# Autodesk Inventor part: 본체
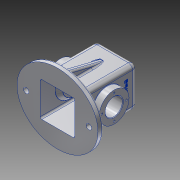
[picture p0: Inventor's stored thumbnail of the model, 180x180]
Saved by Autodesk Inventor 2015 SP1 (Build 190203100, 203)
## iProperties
Created: 2017-07
Part Number: 본체
Material: 알루미늄 6061
Document SubType Name: Modeling
Designer: C04
Density: 2.7 g/cm^3
Appearance: 알루미늄 - 평지
Mass: 889.343 g
Surface Area: 986.145 cm^2
Volume: 329.386 cm^3
Author: C04
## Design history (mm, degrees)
sketch "스케치1"
  geometry: L1 (0, 0)-(-75, 0); L2 (0, 0)-(0, 65); 1 further point; 1 other entity
  constraints: 4 end point, 1 coincident, 1 horizontal, 1 perpendicular, 4 other
  dimensions: "d32" = 75 distance of L1.start L1.end; "d33" = 65 distance of L1.start L2.end
extrude "돌출1" new body sketch "스케치1" distance "d1" = 10; taper "d2" = 0 deg
sketch "스케치7"
  geometry: L1 (-37, 37)-(37, 37); L2 (37, 37)-(37, -37); L3 (37, -37)-(-37, -37); L4 (-37, -37)-(-37, 37); L5 (-37, 37)-(37, -37); L6 (37, 37)-(-37, -37); 1 further point
  constraints: 12 end point, 2 midpoint, 2 parallel, 1 horizontal, 1 perpendicular
  dimensions: "d34" = 74 distance of L2.end L3.end; "d35" = 74 distance of L1.end L2.end
extrude "돌출6" join sketch "스케치7" distance "d36" = 100; taper "d37" = 0 deg
fillet "모깎기3" dims "d38" = 8
sketch "스케치8"
  geometry: L1 (-32, -32)-(32, -32); L2 (32, -32)-(32, 32); L3 (32, 32)-(-32, 32); L4 (-32, 32)-(-32, -32); L5 (-32, -32)-(32, 32); L6 (32, -32)-(-32, 32); 1 further point
  constraints: 12 end point, 2 midpoint, 2 parallel, 1 horizontal, 1 perpendicular
  dimensions: "d39" = 64 distance of L3.end L2.end; "d40" = 64 distance of L2.end L1.end
extrude "돌출7" cut sketch "스케치8" distance "d41" = 105; taper "d42" = 0 deg
sketch "스케치9"
  geometry: L1 (-3, -10)-(61, -10) reference; C1 r 27.5 at (29, 45); 4 further points
  constraints: 1 centre point, 1 midpoint, 1 vertical alignment
  dimensions: "d44" = 55 diameter of C1; "d45" = 55 distance from line of C1.centre L1
extrude "돌출8" join sketch "스케치9" distance "d46" = 13; taper "d47" = 0 deg
sketch "스케치10"
  geometry: L1 (-3, -10)-(61, -10) reference; C1 r 27.5 at (29, 45); 3 further points
  constraints: 1 centre point, 1 vertical alignment
  dimensions: "d48" = 55 diameter of C1; "d49" = 55 distance from line of C1.centre L1
extrude "돌출9" join sketch "스케치10" distance "d50" = 13; taper "d51" = 0 deg
fillet "모깎기5" dims "d52" = 3
sketch "스케치12"
  geometry: L1 (-32, 102)-(-32, 0) reference; L2 (32, 0)-(32, 102) reference; L3 (50, 27.5)-(50, 82.5) reference; L4 (-50, 82.5)-(-50, 27.5) reference; L5 (-32, 55)-(32, 55); L6 (25, 55)-(25, 75.5); L7 (-25, 75.5)-(-25, 55); L8 (-25, 75.5)-(-32, 82.5); L9 (25, 75.5)-(32, 82.5); L10 (29, 0)-(-29, 0) reference; 2 further points
  constraints: 10 end point, 6 point on line, 2 parallel, 1 horizontal alignment, 1 midpoint
  dimensions: "d53" = 7 distance between parallel lines of L2 L6; "d54" = 7 distance between parallel lines of L1 L7; "d55" = 55 diameter of L8.end L5; "d56" = 55 diameter of L9.end L5; "d57" = 135 deg angle of L1 L8; "d58" = 135 deg angle of L2 L9; "d59" = 55 distance between parallel lines of L5 L10 (derived)
revolve "회전2" sketch "스케치12" stored, may be unused: angle "d60" = 90 deg
fillet "모깎기6" dims "d61" = 0.5
sketch "스케치13"
  geometry: C1 r 27.5 at (0, 0) reference; 2 further points
  constraints: 1 vertical alignment
  dimensions: "d62" = 22.5 distance of point (0, 22.5) C1.centre
hole "구멍1" sketch "스케치13" at (0, 22.5) diameter "d63" = 3.242; stored, may be unused: countersink angle "d67" = 90 deg, drill point angle "d69" = 118 deg; dims "d64" = 8, "d65" = 4, "d66" = 2, "d68" = 10
sketch "스케치14"
  geometry: C1 r 20.293 at (0, 0) reference; 2 further points
  constraints: 1 vertical alignment
  dimensions: "d73" = 22.5 distance of C1.centre point (0, 22.5)
hole "구멍2" sketch "스케치14" at (0, 22.5) diameter "d74" = 3.242; stored, may be unused: countersink angle "d78" = 90 deg, drill point angle "d80" = 118 deg; dims "d75" = 8, "d76" = 4, "d77" = 2, "d79" = 10
hole "구멍3" diameter "d86" = 32; stored, may be unused: countersink angle "d90" = 90 deg, drill point angle "d92" = 0 deg; dims "d84" = 10, "d85" = 10, "d87" = 8, "d88" = 4, "d89" = 2, "d91" = 10
sketch "스케치15"
  geometry: L1 (-20, 20)-(20, 20); L2 (20, 20)-(20, -20); L3 (20, -20)-(-20, -20); L4 (-20, -20)-(-20, 20); L5 (-20, 20)-(20, -20); L6 (20, 20)-(-20, -20); 1 further point
  constraints: 12 end point, 2 midpoint, 2 parallel, 1 horizontal, 1 perpendicular
  dimensions: "d134" = 40 distance of L2.end L3.end; "d135" = 40 distance of L1.end L2.end
extrude "돌출10" join sketch "스케치15" distance "d94" = 10; taper "d95" = -5 deg
chamfer "모따기1" distance "d105" = 1; stored, may be unused: second distance "d106" = 2, angle "d107" = 45 deg
sketch "스케치17"
  geometry: 3 further points
  constraints: 2 horizontal alignment
  dimensions: "d108" = 116 distance of point (58, 0) point (-58, 0); "d109" = 58 distance of point (0, 0) point (-58, 0)
hole "구멍5" sketch "스케치17" at (-58, 0), (58, 0) diameter "d110" = 10; stored, may be unused: countersink angle "d114" = 90 deg, drill point angle "d116" = 0 deg; dims "d111" = 8, "d112" = 28, "d113" = 4, "d115" = 30
sketch "스케치18"
  geometry: L1 (10, 55)-(82.194, 37); 1 further point
  constraints: 2 end point
  dimensions: "d119" = 55.78548 distance from line of point (0, 0) L1; "d120" = 90.13802 distance of point (0, 0) L1.end; "d121" = 55.9017 distance of point (0, 0) L1.start; "d122" = 55 vertical distance of point (0, 0) L1.start
feature "리브1" sketch "스케치18" dims "d123" = 1, "d124" = 10, "d125" = 0, "d126" = 0, "d127" = 1, "d128" = 1
fillet "모깎기7" dims "d129" = 3
fillet "모깎기8" dims "d130" = 3
fillet "모깎기9" dims "d131" = 0.5
fillet "모깎기11" dims "d133" = 3
sketch "스케치19"
  geometry: 2 further points
  constraints: 1 coincident
hole "구멍6" sketch "스케치19" at (0, 0) diameter "d136" = 21; stored, may be unused: countersink angle "d140" = 90 deg, drill point angle "d142" = 0 deg; dims "d137" = 8, "d138" = 28, "d139" = 4, "d141" = 30
fillet "모깎기12" dims "d143" = 3
sketch "스케치20"
  geometry: L1 (45.137, 18)-(12.863, 18) reference; L2 (66, -89)-(66, 0) reference; 2 further points
  constraints: 1 other
  dimensions: "d144" = 30 distance from line of L1 point (29, -12); "d145" = 37 distance from line of L2 point (29, -12)
feature "엠보싱1" sketch "스케치20" dims "d146" = 0.5, "d147" = 0
node "솔리드1"
pattern_circular "원형 패턴1" dims angle "d71" = 360 deg
pattern_circular "원형 패턴2" dims angle "d82" = 360 deg
mirror "대칭1"
